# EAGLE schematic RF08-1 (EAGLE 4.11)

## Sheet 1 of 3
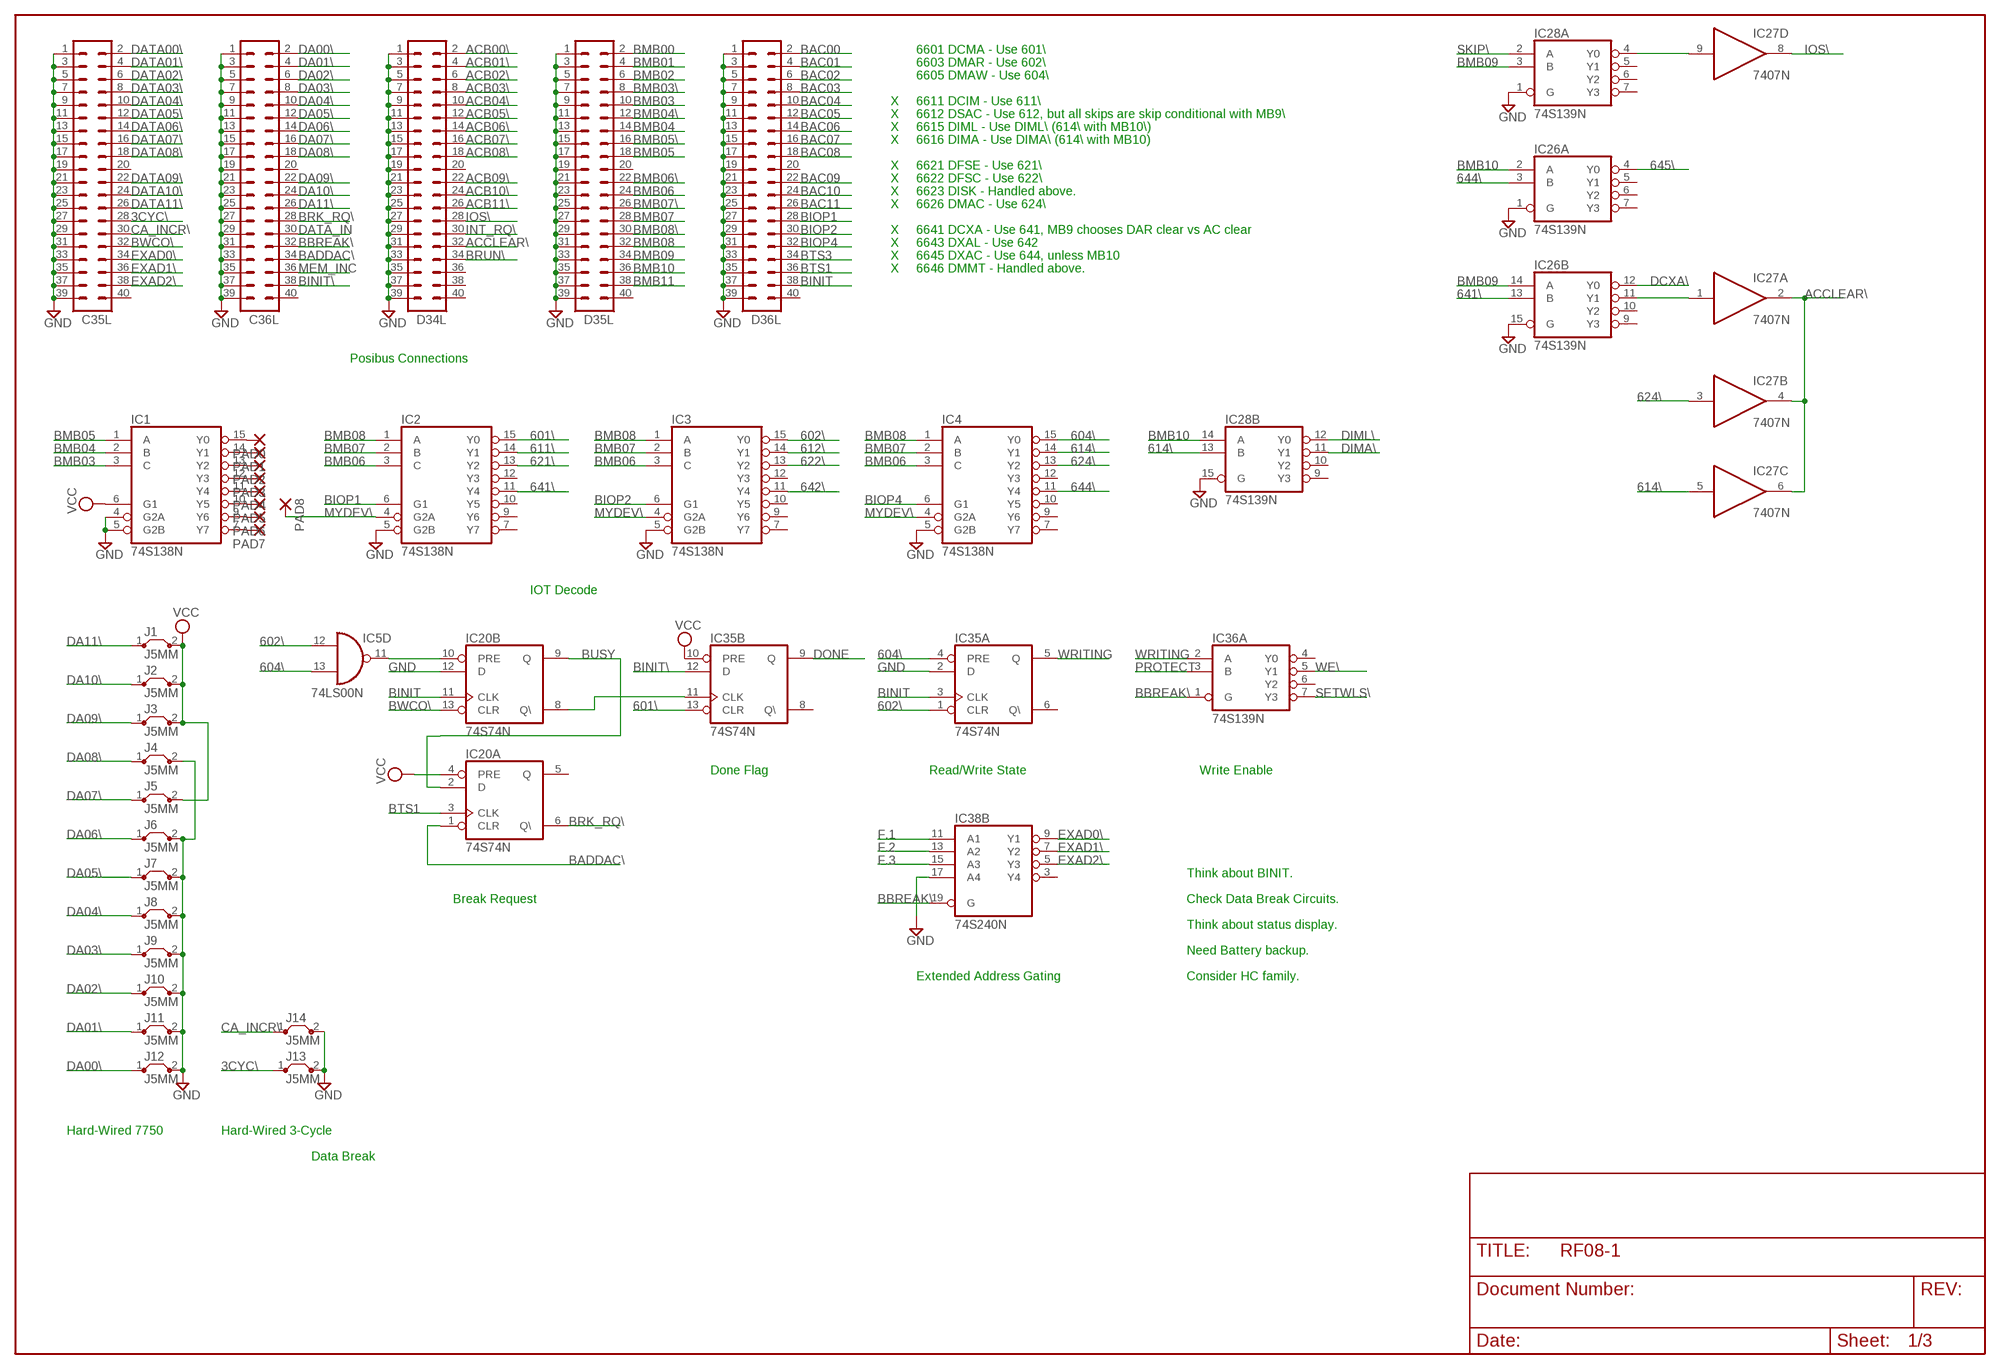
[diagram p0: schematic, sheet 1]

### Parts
C35L  MA20-2  [MA20-2]
C36L  MA20-2  [MA20-2]
D34L  MA20-2  [MA20-2]
D35L  MA20-2  [MA20-2]
D36L  MA20-2  [MA20-2]
IC1  74S138N  [DIL16]
IC2  74S138N  [DIL16]
IC3  74S138N  [DIL16]
IC4  74S138N  [DIL16]
IC5  74LS00N  [DIL14]
IC20  74S74N  [DIL14]
IC26  74S139N  [DIL16]
IC27  7407N  [DIL14]
IC28  74S139N  [DIL16]
IC35  74S74N  [DIL14]
IC36  74S139N  [DIL16]
IC38  74S240N  [DIL20]
J1  J5MM  [05]
J2  J5MM  [05]
J3  J5MM  [05]
J4  J5MM  [05]
J5  J5MM  [05]
J6  J5MM  [05]
J7  J5MM  [05]
J8  J5MM  [05]
J9  J5MM  [05]
J10  J5MM  [05]
J11  J5MM  [05]
J12  J5MM  [05]
J13  J5MM  [05]
J14  J5MM  [05]
PAD0  1,6/0,8  [1,6/0,8]
PAD1  1,6/0,8  [1,6/0,8]
PAD2  1,6/0,8  [1,6/0,8]
PAD3  1,6/0,8  [1,6/0,8]
PAD4  1,6/0,8  [1,6/0,8]
PAD5  1,6/0,8  [1,6/0,8]
PAD6  1,6/0,8  [1,6/0,8]
PAD7  1,6/0,8  [1,6/0,8]
PAD8  1,6/0,8  [1,6/0,8]

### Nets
3CYC\: C35L.28 J13.1
601\: IC2.15(Y0) IC35.13(B:CLR) ; also sheet 2
602\: IC3.15(Y0) IC5.12(D:I0) IC35.1(A:CLR) ; also sheet 2
604\: IC4.15(Y0) IC5.13(D:I1) IC35.4(A:PRE) ; also sheet 2
611\: IC2.14(Y1) ; also sheet 2
612\: IC3.14(Y1) ; also sheet 2
614\: IC4.14(Y1) IC27.5(C:I) IC28.13(B:B)
621\: IC2.13(Y2) ; also sheet 2
622\: IC3.13(Y2) ; also sheet 2
624\: IC4.13(Y2) IC27.3(B:I) ; also sheet 2
641\: IC2.11(Y4) IC26.13(B:B)
642\: IC3.11(Y4) ; also sheet 2
644\: IC4.11(Y4) IC26.3(A:B)
645\: IC26.4(A:Y0) ; also sheet 2
ACB00\: D34L.2 ; also sheet 2
ACB01\: D34L.4 ; also sheet 2
ACB02\: D34L.6 ; also sheet 2
ACB03\: D34L.8 ; also sheet 2
ACB04\: D34L.10 ; also sheet 2
ACB05\: D34L.12 ; also sheet 2
ACB06\: D34L.14 ; also sheet 2
ACB07\: D34L.16 ; also sheet 2
ACB08\: D34L.18 ; also sheet 2
ACB09\: D34L.22 ; also sheet 2
ACB10\: D34L.24 ; also sheet 2
ACB11\: D34L.26 ; also sheet 2
ACCLEAR\: D34L.32 IC27.2(A:O) IC27.4(B:O) IC27.6(C:O)
BAC00: D36L.2 ; also sheet 2
BAC01: D36L.4 ; also sheet 2
BAC02: D36L.6 ; also sheet 2
BAC03: D36L.8 ; also sheet 2
BAC04: D36L.10 ; also sheet 2
BAC05: D36L.12 ; also sheet 2
BAC06: D36L.14 ; also sheet 2
BAC07: D36L.16 ; also sheet 2
BAC08: D36L.18 ; also sheet 2
BAC09: D36L.22 ; also sheet 2
BAC10: D36L.24 ; also sheet 2
BAC11: D36L.26 ; also sheet 2
BADDAC\: C36L.34 IC20.1(A:CLR)
BBREAK\: C36L.32 IC36.1(A:G) IC38.19(B:G) ; also sheet 2,3
BINIT: D36L.38 IC20.11(B:CLK) IC35.3(A:CLK) ; also sheet 2
BINIT\: C36L.38 IC35.12(B:D)
BIOP1: D36L.28 IC2.6(G1)
BIOP2: D36L.30 IC3.6(G1)
BIOP4: D36L.32 IC4.6(G1)
BMB00: D35L.2 ; also sheet 3
BMB01: D35L.4 ; also sheet 3
BMB02: D35L.6 ; also sheet 3
BMB03: D35L.10 IC1.3(C) ; also sheet 3
BMB03\: D35L.8
BMB04: D35L.14 IC1.2(B) ; also sheet 3
BMB04\: D35L.12
BMB05: D35L.18 IC1.1(A) ; also sheet 3
BMB05\: D35L.16
BMB06: D35L.24 IC2.3(C) IC3.3(C) IC4.3(C) ; also sheet 3
BMB06\: D35L.22
BMB07: D35L.28 IC2.2(B) IC3.2(B) IC4.2(B) ; also sheet 3
BMB07\: D35L.26
BMB08: D35L.32 IC2.1(A) IC3.1(A) IC4.1(A) ; also sheet 3
BMB08\: D35L.30
BMB09: D35L.34 IC26.14(B:A) IC28.3(A:B) ; also sheet 3
BMB10: D35L.36 IC26.2(A:A) IC28.14(B:A) ; also sheet 3
BMB11: D35L.38 ; also sheet 3
BRK_RQ\: C36L.28 IC20.6(A:Q\)
BRUN\: D34L.34
BTS1: D36L.36 IC20.3(A:CLK)
BTS3: D36L.34
BUSY: IC20.2(A:D) IC20.9(B:Q) ; also sheet 2
BWCO\: C35L.32 IC20.13(B:CLR)
CA_INCR\: C35L.30 J14.1
DA00\: C36L.2 J12.1
DA01\: C36L.4 J11.1
DA02\: C36L.6 J10.1
DA03\: C36L.8 J9.1
DA04\: C36L.10 J8.1
DA05\: C36L.12 J7.1
DA06\: C36L.14 J6.1
DA07\: C36L.16 J5.1
DA08\: C36L.18 J4.1
DA09\: C36L.22 J3.1
DA10\: C36L.24 J2.1
DA11\: C36L.26 J1.1
DATA00\: C35L.2 ; also sheet 3
DATA01\: C35L.4 ; also sheet 3
DATA02\: C35L.6 ; also sheet 3
DATA03\: C35L.8 ; also sheet 3
DATA04\: C35L.10 ; also sheet 3
DATA05\: C35L.12 ; also sheet 3
DATA06\: C35L.14 ; also sheet 3
DATA07\: C35L.16 ; also sheet 3
DATA08\: C35L.18 ; also sheet 3
DATA09\: C35L.22 ; also sheet 3
DATA10\: C35L.24 ; also sheet 3
DATA11\: C35L.26 ; also sheet 3
DATA_IN: C36L.30
DCXA\: IC26.12(B:Y0) ; also sheet 2
DIMA\: IC28.11(B:Y1) ; also sheet 2
DIML\: IC28.12(B:Y0) ; also sheet 2
DONE: IC35.9(B:Q) ; also sheet 2
EXAD0\: C35L.34 IC38.9(B:Y1)
EXAD1\: C35L.36 IC38.7(B:Y2)
EXAD2\: C35L.38 IC38.5(B:Y3)
F.1: IC38.11(B:A1) ; also sheet 2
F.2: IC38.13(B:A2) ; also sheet 2
F.3: IC38.15(B:A3) ; also sheet 2
GND [Power]: C35L.1 C35L.3 C35L.5 C35L.7 C35L.9 C35L.11 C35L.13 C35L.15 C35L.17 C35L.19 C35L.21 C35L.23 C35L.25 C35L.27 C35L.29 C35L.31 C35L.33 C35L.35 C35L.37 C35L.39 C36L.1 C36L.3 C36L.5 C36L.7 C36L.9 C36L.11 C36L.13 C36L.15 C36L.17 C36L.19 C36L.21 C36L.23 C36L.25 C36L.27 C36L.29 C36L.31 C36L.33 C36L.35 C36L.37 C36L.39 D34L.1 D34L.3 D34L.5 D34L.7 D34L.9 D34L.11 D34L.13 D34L.15 D34L.17 D34L.19 D34L.21 D34L.23 D34L.25 D34L.27 D34L.29 D34L.31 D34L.33 D34L.35 D34L.37 D34L.39 D35L.1 D35L.3 D35L.5 D35L.7 D35L.9 D35L.11 D35L.13 D35L.15 D35L.17 D35L.19 D35L.21 D35L.23 D35L.25 D35L.27 D35L.29 D35L.31 D35L.33 D35L.35 D35L.37 D35L.39 D36L.1 D36L.3 D36L.5 D36L.7 D36L.9 D36L.11 D36L.13 D36L.15 D36L.17 D36L.19 D36L.21 D36L.23 D36L.25 D36L.27 D36L.29 D36L.31 D36L.33 D36L.35 D36L.37 D36L.39 IC1.4(G2A) IC1.5(G2B) IC2.5(G2B) IC3.5(G2B) IC4.5(G2B) IC20.12(B:D) IC26.1(A:G) IC26.15(B:G) IC28.1(A:G) IC28.15(B:G) IC35.2(A:D) IC38.17(B:A4) J4.2 J6.2 J7.2 J8.2 J9.2 J10.2 J11.2 J12.2 J13.2 J14.2 ; also sheet 2,3
INT_RQ\: D34L.30 ; also sheet 2
IOS\: D34L.28 IC27.8(D:O)
MEM_INC: C36L.36
MYDEV\: IC2.4(G2A) IC3.4(G2A) IC4.4(G2A) PAD8.1(P)
N$1: IC1.9(Y6) PAD6.1(P)
N$2: IC20.8(B:Q\) IC35.11(B:CLK)
N$5: IC1.15(Y0) PAD0.1(P)
N$6: IC1.14(Y1) PAD1.1(P)
N$7: IC1.13(Y2) PAD2.1(P)
N$8: IC1.12(Y3) PAD3.1(P)
N$9: IC1.11(Y4) PAD4.1(P)
N$10: IC1.10(Y5) PAD5.1(P)
N$11: IC1.7(Y7) PAD7.1(P)
N$26: IC26.11(B:Y1) IC27.1(A:I)
N$27: IC27.9(D:I) IC28.4(A:Y0)
N$31: IC5.11(D:O) IC20.10(B:PRE)
PROTECT: IC36.3(A:B) ; also sheet 3
SETWLS\: IC36.7(A:Y3) ; also sheet 2
SKIP\: IC28.2(A:A) ; also sheet 2
VCC [Power]: IC1.6(G1) IC20.4(A:PRE) IC35.10(B:PRE) J1.2 J2.2 J3.2 J5.2 ; also sheet 2,3
WE\: IC36.5(A:Y1) ; also sheet 3
WRITING: IC35.5(A:Q) IC36.2(A:A) ; also sheet 3
Unconnected: C35L.20 C35L.40 C36L.20 C36L.40 D34L.20 D34L.36 D34L.38 D34L.40 D35L.20 D35L.40 D36L.20 D36L.40 IC2.7(Y7) IC2.9(Y6) IC2.10(Y5) IC2.12(Y3) IC3.7(Y7) IC3.9(Y6) IC3.10(Y5) IC3.12(Y3) IC4.7(Y7) IC4.9(Y6) IC4.10(Y5) IC4.12(Y3) IC20.5(A:Q) IC26.5(A:Y1) IC26.6(A:Y2) IC26.7(A:Y3) IC26.9(B:Y3) IC26.10(B:Y2) IC27.10(E:O) IC27.11(E:I) IC27.12(F:O) IC27.13(F:I) IC28.5(A:Y1) IC28.6(A:Y2) IC28.7(A:Y3) IC28.9(B:Y3) IC28.10(B:Y2) IC35.6(A:Q\) IC35.8(B:Q\) IC36.4(A:Y0) IC36.6(A:Y2) IC36.9(B:Y3) IC36.10(B:Y2) IC36.11(B:Y1) IC36.12(B:Y0) IC36.13(B:B) IC36.14(B:A) IC36.15(B:G) IC38.1(A:G) IC38.2(A:A1) IC38.3(B:Y4) IC38.4(A:A2) IC38.6(A:A3) IC38.8(A:A4) IC38.12(A:Y4) IC38.14(A:Y3) IC38.16(A:Y2) IC38.18(A:Y1)

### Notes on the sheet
- 6601 DCMA - Use 601\
- 6603 DMAR - Use 602\
- 6605 DMAW - Use 604\
- X | 6611 DCIM - Use 611\
- X | 6612 DSAC - Use 612\, but all skips are skip conditional with MB9\
- X | 6615 DIML - Use DIML\ (614\ with MB10\)
- X | 6616 DIMA - Use DIMA\ (614\ with MB10)
- X | 6621 DFSE - Use 621\
- X | 6622 DFSC - Use 622\
- X | 6623 DISK - Handled above.
- X | 6626 DMAC - Use 624\
- X | 6641 DCXA - Use 641, MB9 chooses DAR clear vs AC clear
- X | 6643 DXAL - Use 642
- X | 6645 DXAC - Use 644, unless MB10
- X | 6646 DMMT - Handled above.
- Posibus Connections
- IOT Decode
- Done Flag | Read/Write State | Write Enable
- Think about BINIT.
- Break Request | Check Data Break Circuits.
- Think about status display.
- Need Battery backup.
- Extended Address Gating | Consider HC family.
- Hard-Wired 7750 | Hard-Wired 3-Cycle
- Data Break

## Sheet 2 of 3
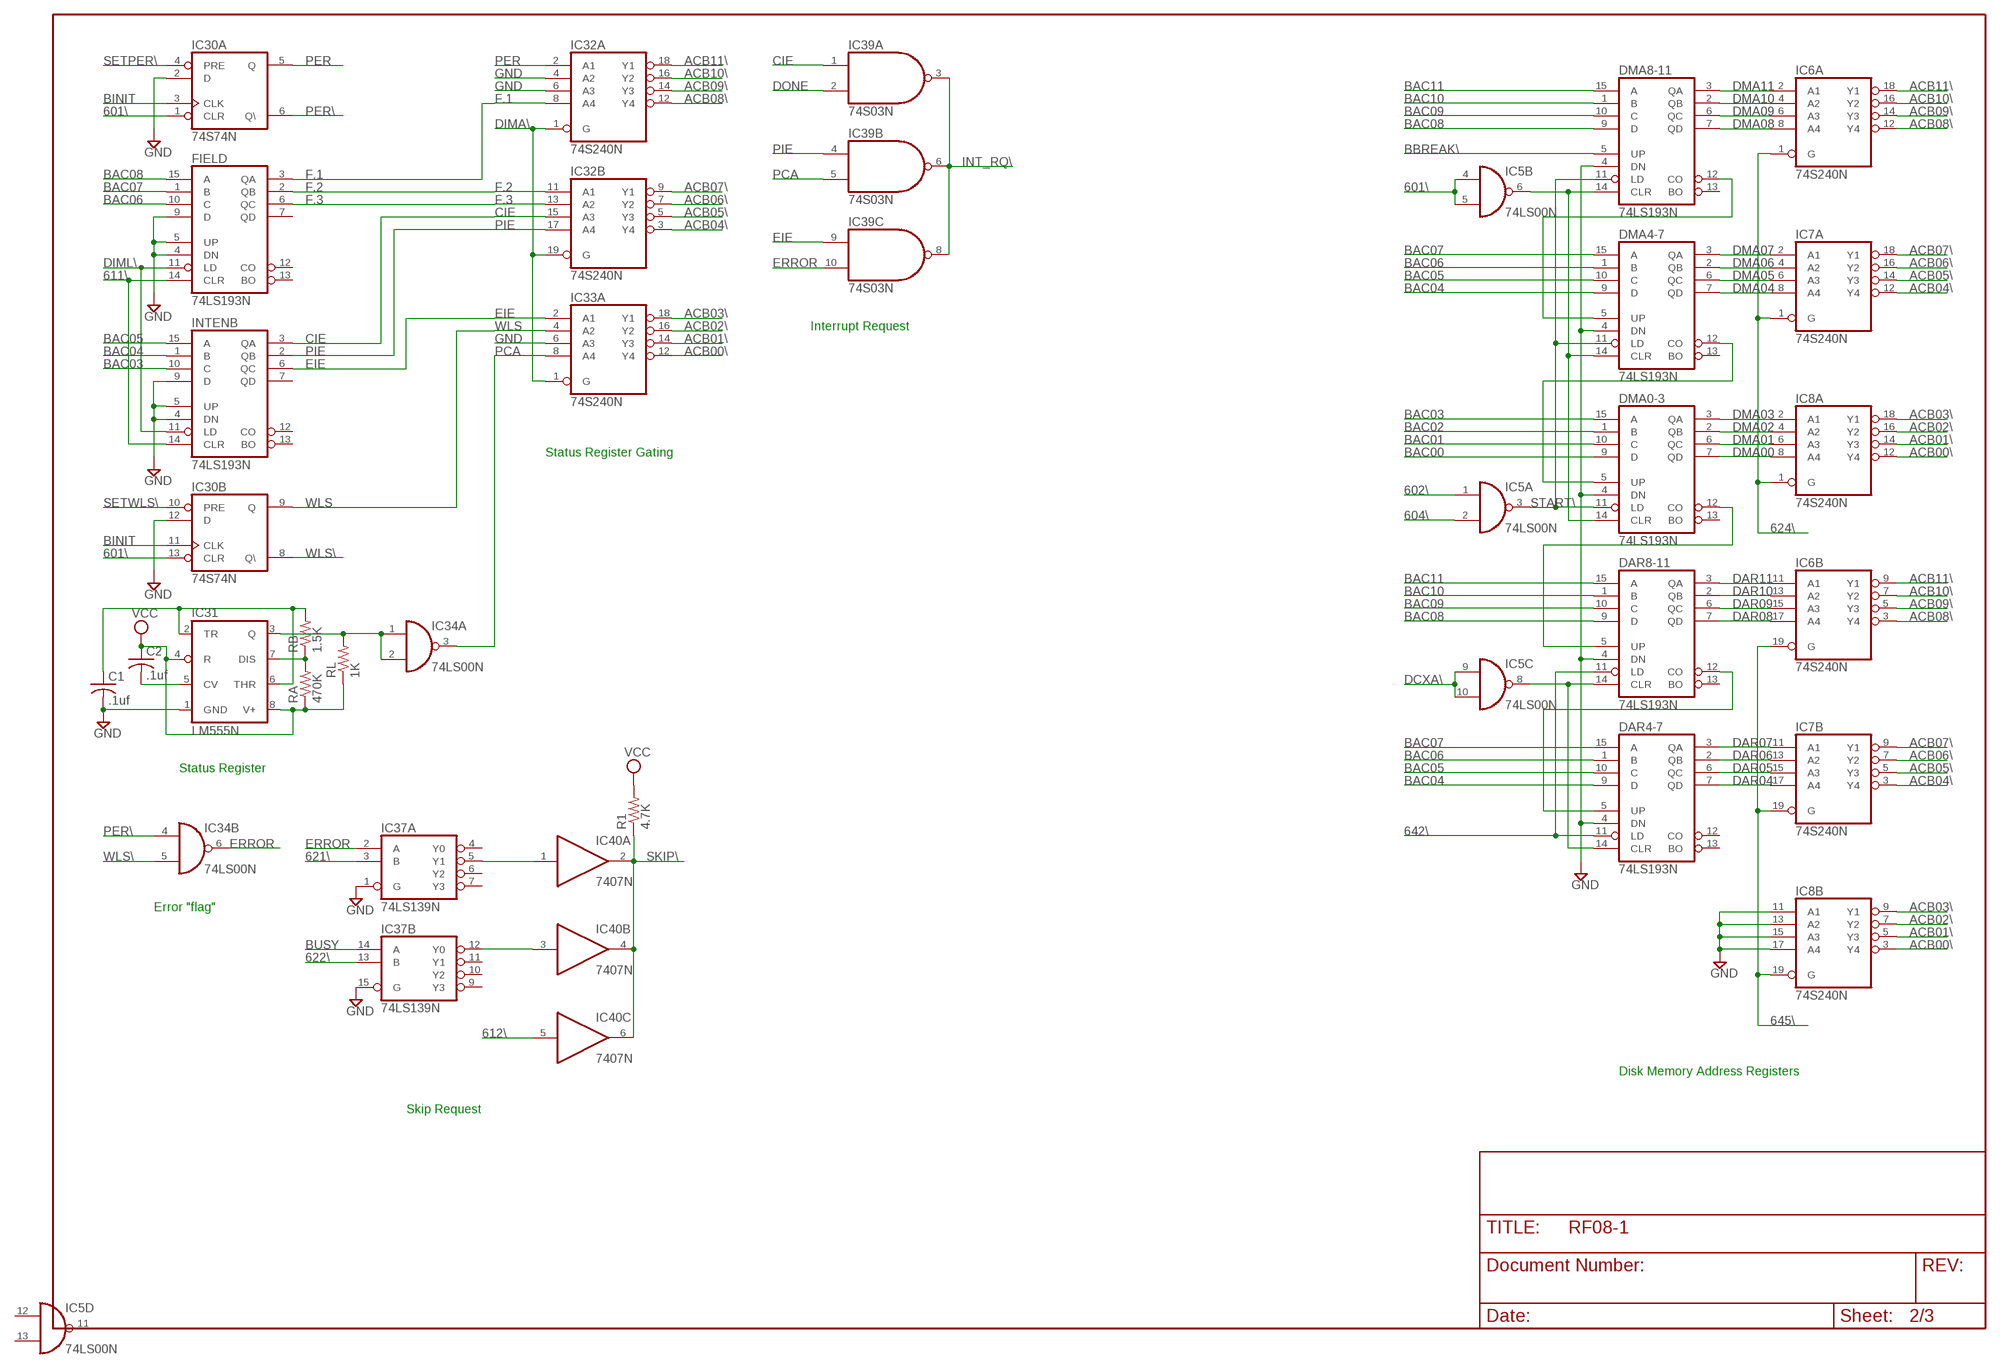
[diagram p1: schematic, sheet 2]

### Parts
C1  .1uf  C-US050-025X075  [C050-025X075]
C2  .1uf  C-US050-025X075  [C050-025X075]
DAR4-7  74LS193N  74LS192N  [DIL16]
DAR8-11  74LS193N  74LS192N  [DIL16]
DMA0-3  74LS193N  74LS192N  [DIL16]
DMA4-7  74LS193N  74LS192N  [DIL16]
DMA8-11  74LS193N  74LS192N  [DIL16]
FIELD  74LS193N  74LS192N  [DIL16]
IC6  74S240N  [DIL20]
IC7  74S240N  [DIL20]
IC8  74S240N  [DIL20]
IC30  74S74N  [DIL14]
IC31  LM555N  [DIL08]
IC32  74S240N  [DIL20]
IC33  74S240N  [DIL20]
IC34  74LS00N  [DIL14]
IC37  74LS139N  [DIL16]
IC39  74S03N  [DIL14]
IC40  7407N  [DIL14]
INTENB  74LS193N  74LS192N  [DIL16]
R1  4.7K  R-US_0207/10  [0207/10]
RA  470K  R-US_0207/10  [0207/10]
RB  1.5K  R-US_0207/10  [0207/10]
RL  1K  R-US_0207/10  [0207/10]

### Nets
601\: IC5.4(B:I0) IC5.5(B:I1) IC30.1(A:CLR) IC30.13(B:CLR) ; also sheet 1
602\: IC5.1(A:I0) ; also sheet 1
604\: IC5.2(A:I1) ; also sheet 1
611\: FIELD.14(CLR) INTENB.14(CLR) ; also sheet 1
612\: IC40.5(C:I) ; also sheet 1
621\: IC37.3(A:B) ; also sheet 1
622\: IC37.13(B:B) ; also sheet 1
624\: IC6.1(A:G) IC7.1(A:G) IC8.1(A:G) ; also sheet 1
642\: DAR4-7.11(LD) DAR8-11.11(LD) ; also sheet 1
645\: IC6.19(B:G) IC7.19(B:G) IC8.19(B:G) ; also sheet 1
ACB00\: IC8.3(B:Y4) IC8.12(A:Y4) IC33.12(A:Y4) ; also sheet 1
ACB01\: IC8.5(B:Y3) IC8.14(A:Y3) IC33.14(A:Y3) ; also sheet 1
ACB02\: IC8.7(B:Y2) IC8.16(A:Y2) IC33.16(A:Y2) ; also sheet 1
ACB03\: IC8.9(B:Y1) IC8.18(A:Y1) IC33.18(A:Y1) ; also sheet 1
ACB04\: IC7.3(B:Y4) IC7.12(A:Y4) IC32.3(B:Y4) ; also sheet 1
ACB05\: IC7.5(B:Y3) IC7.14(A:Y3) IC32.5(B:Y3) ; also sheet 1
ACB06\: IC7.7(B:Y2) IC7.16(A:Y2) IC32.7(B:Y2) ; also sheet 1
ACB07\: IC7.9(B:Y1) IC7.18(A:Y1) IC32.9(B:Y1) ; also sheet 1
ACB08\: IC6.3(B:Y4) IC6.12(A:Y4) IC32.12(A:Y4) ; also sheet 1
ACB09\: IC6.5(B:Y3) IC6.14(A:Y3) IC32.14(A:Y3) ; also sheet 1
ACB10\: IC6.7(B:Y2) IC6.16(A:Y2) IC32.16(A:Y2) ; also sheet 1
ACB11\: IC6.9(B:Y1) IC6.18(A:Y1) IC32.18(A:Y1) ; also sheet 1
BAC00: DMA0-3.9(D) ; also sheet 1
BAC01: DMA0-3.10(C) ; also sheet 1
BAC02: DMA0-3.1(B) ; also sheet 1
BAC03: DMA0-3.15(A) INTENB.10(C) ; also sheet 1
BAC04: DAR4-7.9(D) DMA4-7.9(D) INTENB.1(B) ; also sheet 1
BAC05: DAR4-7.10(C) DMA4-7.10(C) INTENB.15(A) ; also sheet 1
BAC06: DAR4-7.1(B) DMA4-7.1(B) FIELD.10(C) ; also sheet 1
BAC07: DAR4-7.15(A) DMA4-7.15(A) FIELD.1(B) ; also sheet 1
BAC08: DAR8-11.9(D) DMA8-11.9(D) FIELD.15(A) ; also sheet 1
BAC09: DAR8-11.10(C) DMA8-11.10(C) ; also sheet 1
BAC10: DAR8-11.1(B) DMA8-11.1(B) ; also sheet 1
BAC11: DAR8-11.15(A) DMA8-11.15(A) ; also sheet 1
BBREAK\: DMA8-11.5(UP) ; also sheet 1,3
BINIT: IC30.3(A:CLK) IC30.11(B:CLK) ; also sheet 1
BUSY: IC37.14(B:A) ; also sheet 1
CIE: IC32.15(B:A3) IC39.1(A:I0) INTENB.3(QA)
DAR04: DAR4-7.7(QD) IC7.17(B:A4) ; also sheet 3
DAR05: DAR4-7.6(QC) IC7.15(B:A3) ; also sheet 3
DAR06: DAR4-7.2(QB) IC7.13(B:A2) ; also sheet 3
DAR07: DAR4-7.3(QA) IC7.11(B:A1) ; also sheet 3
DAR08: DAR8-11.7(QD) IC6.17(B:A4) ; also sheet 3
DAR09: DAR8-11.6(QC) IC6.15(B:A3) ; also sheet 3
DAR10: DAR8-11.2(QB) IC6.13(B:A2) ; also sheet 3
DAR11: DAR8-11.3(QA) IC6.11(B:A1) ; also sheet 3
DCXA\: IC5.9(C:I0) IC5.10(C:I1) ; also sheet 1
DIMA\: IC32.1(A:G) IC32.19(B:G) IC33.1(A:G) ; also sheet 1
DIML\: FIELD.11(LD) INTENB.11(LD) ; also sheet 1
DMA00: DMA0-3.7(QD) IC8.8(A:A4) ; also sheet 3
DMA01: DMA0-3.6(QC) IC8.6(A:A3) ; also sheet 3
DMA02: DMA0-3.2(QB) IC8.4(A:A2) ; also sheet 3
DMA03: DMA0-3.3(QA) IC8.2(A:A1) ; also sheet 3
DMA04: DMA4-7.7(QD) IC7.8(A:A4) ; also sheet 3
DMA05: DMA4-7.6(QC) IC7.6(A:A3) ; also sheet 3
DMA06: DMA4-7.2(QB) IC7.4(A:A2) ; also sheet 3
DMA07: DMA4-7.3(QA) IC7.2(A:A1) ; also sheet 3
DMA08: DMA8-11.7(QD) IC6.8(A:A4) ; also sheet 3
DMA09: DMA8-11.6(QC) IC6.6(A:A3) ; also sheet 3
DMA10: DMA8-11.2(QB) IC6.4(A:A2) ; also sheet 3
DMA11: DMA8-11.3(QA) IC6.2(A:A1) ; also sheet 3
DONE: IC39.2(A:I1) ; also sheet 1
EIE: IC33.2(A:A1) IC39.9(C:I0) INTENB.6(QC)
ERROR: IC34.6(B:O) IC37.2(A:A) IC39.10(C:I1)
F.1: FIELD.3(QA) IC32.8(A:A4) ; also sheet 1
F.2: FIELD.2(QB) IC32.11(B:A1) ; also sheet 1
F.3: FIELD.6(QC) IC32.13(B:A2) ; also sheet 1
GND [Power]: C1.2 DAR4-7.4(DN) DAR8-11.4(DN) DMA0-3.4(DN) DMA4-7.4(DN) DMA8-11.4(DN) FIELD.4(DN) FIELD.5(UP) FIELD.9(D) IC8.11(B:A1) IC8.13(B:A2) IC8.15(B:A3) IC8.17(B:A4) IC30.2(A:D) IC30.12(B:D) IC31.1(GND) IC32.4(A:A2) IC32.6(A:A3) IC33.6(A:A3) IC37.1(A:G) IC37.15(B:G) INTENB.4(DN) INTENB.5(UP) INTENB.9(D) ; also sheet 1,3
INT_RQ\: IC39.3(A:O) IC39.6(B:O) IC39.8(C:O) ; also sheet 1
N$3: DMA0-3.5(UP) DMA4-7.12(CO)
N$12: DAR4-7.14(CLR) DAR8-11.14(CLR) IC5.8(C:O)
N$13: DMA4-7.5(UP) DMA8-11.12(CO)
N$16: DAR8-11.5(UP) DMA0-3.12(CO)
N$22: DMA0-3.14(CLR) DMA4-7.14(CLR) DMA8-11.14(CLR) IC5.6(B:O)
N$25: DAR4-7.5(UP) DAR8-11.12(CO)
N$28: IC37.5(A:Y1) IC40.1(A:I)
N$29: IC31.7(DIS) RA.2 RB.1
N$30: IC31.3(Q) IC34.1(A:I0) IC34.2(A:I1) RL.2
N$32: C1.1 IC31.2(TR) IC31.6(THR) RB.2
N$33: IC37.12(B:Y0) IC40.3(B:I)
N$34: C2.2 IC31.5(CV)
PCA: IC33.8(A:A4) IC34.3(A:O) IC39.5(B:I1)
PER: IC30.5(A:Q) IC32.2(A:A1)
PER\: IC30.6(A:Q\) IC34.4(B:I0)
PIE: IC32.17(B:A4) IC39.4(B:I0) INTENB.2(QB)
SETPER\: IC30.4(A:PRE) ; also sheet 3
SETWLS\: IC30.10(B:PRE) ; also sheet 1
SKIP\: IC40.2(A:O) IC40.4(B:O) IC40.6(C:O) R1.1 ; also sheet 1
START\: DMA0-3.11(LD) DMA4-7.11(LD) DMA8-11.11(LD) IC5.3(A:O)
VCC [Power]: C2.1 IC31.4(R) IC31.8(V+) R1.2 RA.1 RL.1 ; also sheet 1,3
WLS: IC30.9(B:Q) IC33.4(A:A2)
WLS\: IC30.8(B:Q\) IC34.5(B:I1)
Unconnected: DAR4-7.12(CO) DAR4-7.13(BO) DAR8-11.13(BO) DMA0-3.13(BO) DMA4-7.13(BO) DMA8-11.13(BO) FIELD.7(QD) FIELD.12(CO) FIELD.13(BO) IC33.3(B:Y4) IC33.5(B:Y3) IC33.7(B:Y2) IC33.9(B:Y1) IC33.11(B:A1) IC33.13(B:A2) IC33.15(B:A3) IC33.17(B:A4) IC33.19(B:G) IC34.8(C:O) IC34.9(C:I0) IC34.10(C:I1) IC34.11(D:O) IC34.12(D:I0) IC34.13(D:I1) IC37.4(A:Y0) IC37.6(A:Y2) IC37.7(A:Y3) IC37.9(B:Y3) IC37.10(B:Y2) IC37.11(B:Y1) IC39.11(D:O) IC39.12(D:I0) IC39.13(D:I1) IC40.8(D:O) IC40.9(D:I) IC40.10(E:O) IC40.11(E:I) IC40.12(F:O) IC40.13(F:I) INTENB.7(QD) INTENB.12(CO) INTENB.13(BO)

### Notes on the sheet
- Interrupt Request
- Status Register Gating
- Status Register
- Error "flag"
- Disk Memory Address Registers
- Skip Request

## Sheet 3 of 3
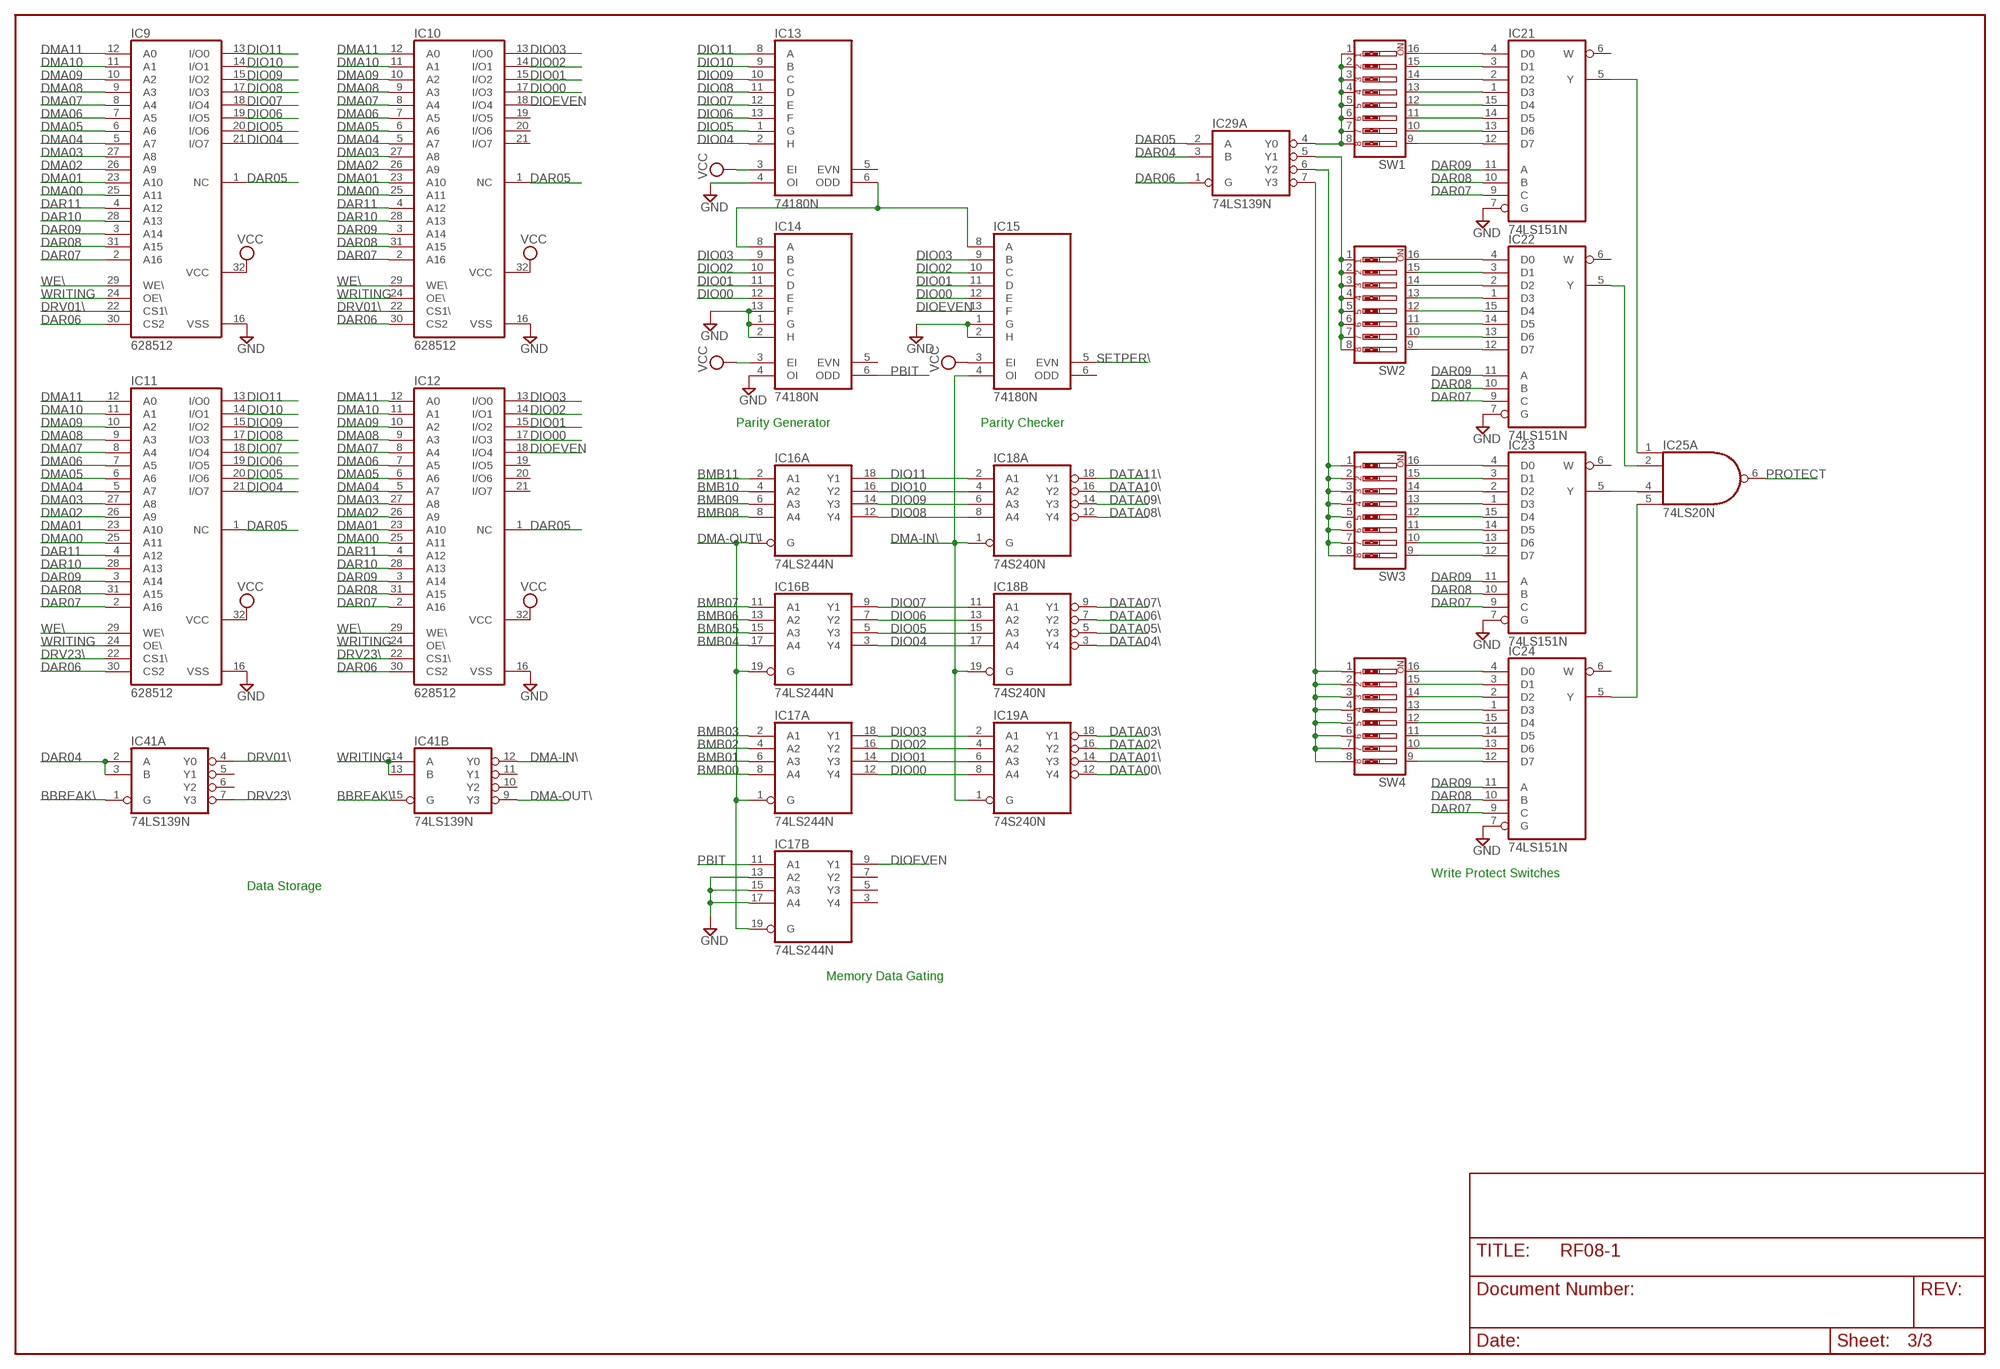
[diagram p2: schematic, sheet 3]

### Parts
IC9  628512  628128P  [DIL32]
IC10  628512  628128P  [DIL32]
IC11  628512  628128P  [DIL32]
IC12  628512  628128P  [DIL32]
IC13  74180N  [DIL14]
IC14  74180N  [DIL14]
IC15  74180N  [DIL14]
IC16  74LS244N  [DIL20]
IC17  74LS244N  [DIL20]
IC18  74S240N  [DIL20]
IC19  74S240N  [DIL20]
IC21  74LS151N  [DIL16]
IC22  74LS151N  [DIL16]
IC23  74LS151N  [DIL16]
IC24  74LS151N  [DIL16]
IC25  74LS20N  [DIL14]
IC29  74LS139N  [DIL16]
IC41  74LS139N  [DIL16]
SW1  SW_DIP-8  [EDG-08]
SW2  SW_DIP-8  [EDG-08]
SW3  SW_DIP-8  [EDG-08]
SW4  SW_DIP-8  [EDG-08]

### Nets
BBREAK\: IC41.1(A:G) IC41.15(B:G) ; also sheet 1,2
BMB00: IC17.8(A:A4) ; also sheet 1
BMB01: IC17.6(A:A3) ; also sheet 1
BMB02: IC17.4(A:A2) ; also sheet 1
BMB03: IC17.2(A:A1) ; also sheet 1
BMB04: IC16.17(B:A4) ; also sheet 1
BMB05: IC16.15(B:A3) ; also sheet 1
BMB06: IC16.13(B:A2) ; also sheet 1
BMB07: IC16.11(B:A1) ; also sheet 1
BMB08: IC16.8(A:A4) ; also sheet 1
BMB09: IC16.6(A:A3) ; also sheet 1
BMB10: IC16.4(A:A2) ; also sheet 1
BMB11: IC16.2(A:A1) ; also sheet 1
DAR04: IC29.3(A:B) IC41.2(A:A) IC41.3(A:B) ; also sheet 2
DAR05: IC9.1(NC) IC10.1(NC) IC11.1(NC) IC12.1(NC) IC29.2(A:A) ; also sheet 2
DAR06: IC9.30(CS2) IC10.30(CS2) IC11.30(CS2) IC12.30(CS2) IC29.1(A:G) ; also sheet 2
DAR07: IC9.2(A16) IC10.2(A16) IC11.2(A16) IC12.2(A16) IC21.9(C) IC22.9(C) IC23.9(C) IC24.9(C) ; also sheet 2
DAR08: IC9.31(A15) IC10.31(A15) IC11.31(A15) IC12.31(A15) IC21.10(B) IC22.10(B) IC23.10(B) IC24.10(B) ; also sheet 2
DAR09: IC9.3(A14) IC10.3(A14) IC11.3(A14) IC12.3(A14) IC21.11(A) IC22.11(A) IC23.11(A) IC24.11(A) ; also sheet 2
DAR10: IC9.28(A13) IC10.28(A13) IC11.28(A13) IC12.28(A13) ; also sheet 2
DAR11: IC9.4(A12) IC10.4(A12) IC11.4(A12) IC12.4(A12) ; also sheet 2
DATA00\: IC19.12(A:Y4) ; also sheet 1
DATA01\: IC19.14(A:Y3) ; also sheet 1
DATA02\: IC19.16(A:Y2) ; also sheet 1
DATA03\: IC19.18(A:Y1) ; also sheet 1
DATA04\: IC18.3(B:Y4) ; also sheet 1
DATA05\: IC18.5(B:Y3) ; also sheet 1
DATA06\: IC18.7(B:Y2) ; also sheet 1
DATA07\: IC18.9(B:Y1) ; also sheet 1
DATA08\: IC18.12(A:Y4) ; also sheet 1
DATA09\: IC18.14(A:Y3) ; also sheet 1
DATA10\: IC18.16(A:Y2) ; also sheet 1
DATA11\: IC18.18(A:Y1) ; also sheet 1
DIO00: IC10.17(I/O3) IC12.17(I/O3) IC14.12(E) IC15.12(E) IC17.12(A:Y4) IC19.8(A:A4)
DIO01: IC10.15(I/O2) IC12.15(I/O2) IC14.11(D) IC15.11(D) IC17.14(A:Y3) IC19.6(A:A3)
DIO02: IC10.14(I/O1) IC12.14(I/O1) IC14.10(C) IC15.10(C) IC17.16(A:Y2) IC19.4(A:A2)
DIO03: IC10.13(I/O0) IC12.13(I/O0) IC14.9(B) IC15.9(B) IC17.18(A:Y1) IC19.2(A:A1)
DIO04: IC9.21(I/O7) IC11.21(I/O7) IC13.2(H) IC16.3(B:Y4) IC18.17(B:A4)
DIO05: IC9.20(I/O6) IC11.20(I/O6) IC13.1(G) IC16.5(B:Y3) IC18.15(B:A3)
DIO06: IC9.19(I/O5) IC11.19(I/O5) IC13.13(F) IC16.7(B:Y2) IC18.13(B:A2)
DIO07: IC9.18(I/O4) IC11.18(I/O4) IC13.12(E) IC16.9(B:Y1) IC18.11(B:A1)
DIO08: IC9.17(I/O3) IC11.17(I/O3) IC13.11(D) IC16.12(A:Y4) IC18.8(A:A4)
DIO09: IC9.15(I/O2) IC11.15(I/O2) IC13.10(C) IC16.14(A:Y3) IC18.6(A:A3)
DIO10: IC9.14(I/O1) IC11.14(I/O1) IC13.9(B) IC16.16(A:Y2) IC18.4(A:A2)
DIO11: IC9.13(I/O0) IC11.13(I/O0) IC13.8(A) IC16.18(A:Y1) IC18.2(A:A1)
DIOEVEN: IC10.18(I/O4) IC12.18(I/O4) IC15.13(F) IC17.9(B:Y1)
DMA00: IC9.25(A11) IC10.25(A11) IC11.25(A11) IC12.25(A11) ; also sheet 2
DMA01: IC9.23(A10) IC10.23(A10) IC11.23(A10) IC12.23(A10) ; also sheet 2
DMA02: IC9.26(A9) IC10.26(A9) IC11.26(A9) IC12.26(A9) ; also sheet 2
DMA03: IC9.27(A8) IC10.27(A8) IC11.27(A8) IC12.27(A8) ; also sheet 2
DMA04: IC9.5(A7) IC10.5(A7) IC11.5(A7) IC12.5(A7) ; also sheet 2
DMA05: IC9.6(A6) IC10.6(A6) IC11.6(A6) IC12.6(A6) ; also sheet 2
DMA06: IC9.7(A5) IC10.7(A5) IC11.7(A5) IC12.7(A5) ; also sheet 2
DMA07: IC9.8(A4) IC10.8(A4) IC11.8(A4) IC12.8(A4) ; also sheet 2
DMA08: IC9.9(A3) IC10.9(A3) IC11.9(A3) IC12.9(A3) ; also sheet 2
DMA09: IC9.10(A2) IC10.10(A2) IC11.10(A2) IC12.10(A2) ; also sheet 2
DMA10: IC9.11(A1) IC10.11(A1) IC11.11(A1) IC12.11(A1) ; also sheet 2
DMA11: IC9.12(A0) IC10.12(A0) IC11.12(A0) IC12.12(A0) ; also sheet 2
DMA-IN\: IC15.4(OI) IC18.1(A:G) IC18.19(B:G) IC19.1(A:G) IC41.12(B:Y0)
DMA-OUT\: IC16.1(A:G) IC16.19(B:G) IC17.1(A:G) IC17.19(B:G) IC41.9(B:Y3)
DRV01\: IC9.22(CS1\) IC10.22(CS1\) IC41.4(A:Y0)
DRV23\: IC11.22(CS1\) IC12.22(CS1\) IC41.7(A:Y3)
GND [Power]: IC9.16(VSS) IC10.16(VSS) IC11.16(VSS) IC12.16(VSS) IC13.4(OI) IC14.1(G) IC14.2(H) IC14.4(OI) IC14.13(F) IC15.1(G) IC15.2(H) IC17.13(B:A2) IC17.15(B:A3) IC17.17(B:A4) IC21.7(G) IC22.7(G) IC23.7(G) IC24.7(G) ; also sheet 1,2
N$4: IC29.4(A:Y0) SW1.1 SW1.2 SW1.3 SW1.4 SW1.5 SW1.6 SW1.7 SW1.8
N$14: IC13.6(ODD) IC14.8(A) IC15.8(A)
N$15: IC22.5(Y) IC25.2(A:I1)
N$17: IC29.5(A:Y1) SW2.1 SW2.2 SW2.3 SW2.4 SW2.5 SW2.6 SW2.7 SW2.8
N$19: IC29.6(A:Y2) SW3.1 SW3.2 SW3.3 SW3.4 SW3.5 SW3.6 SW3.7 SW3.8
N$20: IC29.7(A:Y3) SW4.1 SW4.2 SW4.3 SW4.4 SW4.5 SW4.6 SW4.7 SW4.8
N$21: IC23.5(Y) IC25.4(A:I2)
N$23: IC21.5(Y) IC25.1(A:I0)
N$24: IC24.5(Y) IC25.5(A:I3)
N$53: IC21.4(D0) SW1.16
N$54: IC21.3(D1) SW1.15
N$55: IC21.2(D2) SW1.14
N$56: IC21.1(D3) SW1.13
N$57: IC21.14(D5) SW1.11
N$58: IC21.13(D6) SW1.10
N$59: IC21.12(D7) SW1.9
N$60: IC21.15(D4) SW1.12
N$61: IC22.4(D0) SW2.16
N$62: IC22.3(D1) SW2.15
N$63: IC22.2(D2) SW2.14
N$64: IC22.1(D3) SW2.13
N$65: IC22.14(D5) SW2.11
N$66: IC22.13(D6) SW2.10
N$67: IC22.12(D7) SW2.9
N$68: IC23.4(D0) SW3.16
N$69: IC23.3(D1) SW3.15
N$70: IC23.2(D2) SW3.14
N$71: IC23.1(D3) SW3.13
N$72: IC23.14(D5) SW3.11
N$73: IC23.13(D6) SW3.10
N$74: IC23.12(D7) SW3.9
N$75: IC24.4(D0) SW4.16
N$76: IC24.3(D1) SW4.15
N$77: IC24.2(D2) SW4.14
N$78: IC24.1(D3) SW4.13
N$79: IC24.14(D5) SW4.11
N$80: IC24.13(D6) SW4.10
N$81: IC24.12(D7) SW4.9
N$82: IC24.15(D4) SW4.12
N$83: IC23.15(D4) SW3.12
N$84: IC22.15(D4) SW2.12
PBIT: IC14.6(ODD) IC17.11(B:A1)
PROTECT: IC25.6(A:O) ; also sheet 1
SETPER\: IC15.5(EVN) ; also sheet 2
VCC [Power]: IC9.32(VCC) IC10.32(VCC) IC11.32(VCC) IC12.32(VCC) IC13.3(EI) IC14.3(EI) IC15.3(EI) ; also sheet 1,2
WE\: IC9.29(WE\) IC10.29(WE\) IC11.29(WE\) IC12.29(WE\) ; also sheet 1
WRITING: IC9.24(OE\) IC10.24(OE\) IC11.24(OE\) IC12.24(OE\) IC41.13(B:B) IC41.14(B:A) ; also sheet 1
Unconnected: IC10.19(I/O5) IC10.20(I/O6) IC10.21(I/O7) IC12.19(I/O5) IC12.20(I/O6) IC12.21(I/O7) IC13.5(EVN) IC14.5(EVN) IC15.6(ODD) IC17.3(B:Y4) IC17.5(B:Y3) IC17.7(B:Y2) IC19.3(B:Y4) IC19.5(B:Y3) IC19.7(B:Y2) IC19.9(B:Y1) IC19.11(B:A1) IC19.13(B:A2) IC19.15(B:A3) IC19.17(B:A4) IC19.19(B:G) IC21.6(W) IC22.6(W) IC23.6(W) IC24.6(W) IC25.8(B:O) IC25.9(B:I0) IC25.10(B:I1) IC25.12(B:I2) IC25.13(B:I3) IC29.9(B:Y3) IC29.10(B:Y2) IC29.11(B:Y1) IC29.12(B:Y0) IC29.13(B:B) IC29.14(B:A) IC29.15(B:G) IC41.5(A:Y1) IC41.6(A:Y2) IC41.10(B:Y2) IC41.11(B:Y1)

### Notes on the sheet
- Parity Generator | Parity Checker
- Write Protect Switches
- Data Storage
- Memory Data Gating

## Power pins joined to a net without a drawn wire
GND: DAR4-7.8(GND) DAR8-11.8(GND) DMA0-3.8(GND) DMA4-7.8(GND) DMA8-11.8(GND) FIELD.8(GND) IC1.8(GND) IC2.8(GND) IC3.8(GND) IC4.8(GND) IC5.7(P:GND) IC6.10(P:GND) IC7.10(P:GND) IC8.10(P:GND) IC13.7(GND) IC14.7(GND) IC15.7(GND) IC16.10(P:GND) IC17.10(P:GND) IC18.10(P:GND) IC19.10(P:GND) IC20.7(P:GND) IC21.8(GND) IC22.8(GND) IC23.8(GND) IC24.8(GND) IC25.7(P:GND) IC26.8(P:GND) IC27.7(P:GND) IC28.8(P:GND) IC29.8(P:GND) IC30.7(P:GND) IC32.10(P:GND) IC33.10(P:GND) IC34.7(P:GND) IC35.7(P:GND) IC36.8(P:GND) IC37.8(P:GND) IC38.10(P:GND) IC39.7(P:GND) IC40.7(P:GND) IC41.8(P:GND) INTENB.8(GND)
VCC: DAR4-7.16(VCC) DAR8-11.16(VCC) DMA0-3.16(VCC) DMA4-7.16(VCC) DMA8-11.16(VCC) FIELD.16(VCC) IC1.16(VCC) IC2.16(VCC) IC3.16(VCC) IC4.16(VCC) IC5.14(P:VCC) IC6.20(P:VCC) IC7.20(P:VCC) IC8.20(P:VCC) IC13.14(VCC) IC14.14(VCC) IC15.14(VCC) IC16.20(P:VCC) IC17.20(P:VCC) IC18.20(P:VCC) IC19.20(P:VCC) IC20.14(P:VCC) IC21.16(VCC) IC22.16(VCC) IC23.16(VCC) IC24.16(VCC) IC25.14(P:VCC) IC26.16(P:VCC) IC27.14(P:VCC) IC28.16(P:VCC) IC29.16(P:VCC) IC30.14(P:VCC) IC32.20(P:VCC) IC33.20(P:VCC) IC34.14(P:VCC) IC35.14(P:VCC) IC36.16(P:VCC) IC37.16(P:VCC) IC38.20(P:VCC) IC39.14(P:VCC) IC40.14(P:VCC) IC41.16(P:VCC) INTENB.16(VCC)

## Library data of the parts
C1 C2 = rcl:C-US: CAPACITOR, American symbol
C35L C36L D34L D35L D36L = con-lstb:MA20-2: PIN HEADER
DAR4-7 DAR8-11 DMA0-3 DMA4-7 DMA8-11 FIELD INTENB = 74xx-us:74*192: Synchronous 4-bit UP/DOWN COUNTER
IC1-IC4 = 74xx-us:74*138: 3-line to 8-line DECODER/DEMULTIPLEXER
IC5 IC34 = 74xx-eu:74*00: Quad 2-input NAND gate
IC6-IC8 IC18 IC19 IC32 IC33 IC38 = 74xx-us:74*240: Octal BUFFER and LINE DRIVER, 3-state
IC9-IC12 = memory-hitachi:628128P: MEMORY
IC13-IC15 = 74xx-us:74*180: 9-bit odd/even PARITY GENERATOR/CHECKER
IC16 IC17 = 74xx-us:74*244: Octal BUFFER and LINE DRIVER, 3-state
IC20 IC30 IC35 = 74xx-us:74*74: Dual D type positive edge triggered FLIP FLOP, preset and clear
IC21-IC24 = 74xx-eu:74*151: Data SELECTOR/MULTIPLEXER
IC25 = 74xx-us:74*20: Dual 4-input NAND gate
IC26 IC28 IC29 IC36 IC37 IC41 = 74xx-us:74*139: Dual 2-line to 4-line DECODER/DEMULTIPLEXER
IC27 IC40 = 74xx-us:74*07: Hex BUFFER, open collector high-voltage output
IC31 = linear:*555: TIMER
IC39 = 74xx-us:74*03: Quad 2-input NAND gate, open collector output
J1-J14 = jumper:J: Bridge
PAD0 PAD1-PAD8 = wirepad:1,6/0,8: THROUGH-HOLE PAD
R1 RA RB RL = rcl:R-US_: RESISTOR, American symbol
SW1-SW4 = special:SW_DIP-8: DIP SWITCH

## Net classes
1 Power: width 0.508 mm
